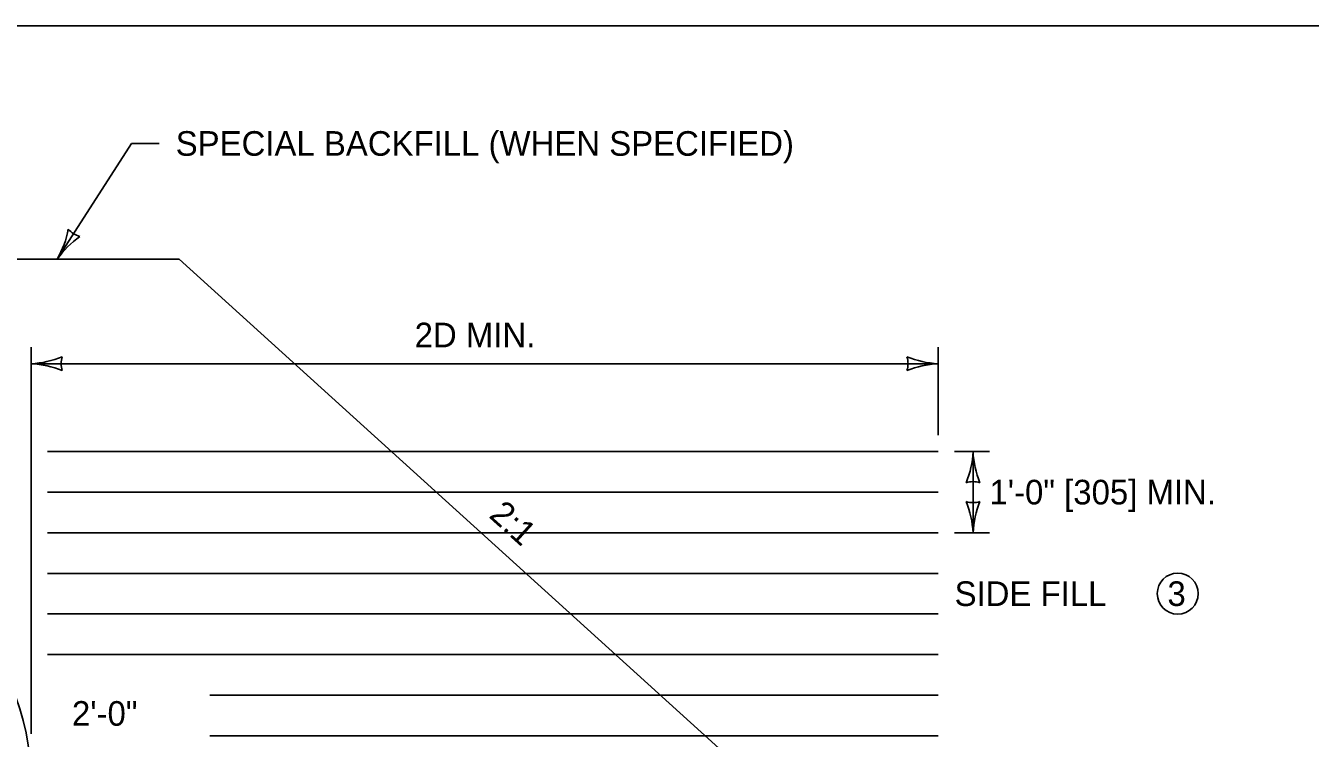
# Model space of a CAD drawing. Extents: x 49991.4 to 50021, y 49987.6 to 50011.4.
# Drawn here: x 50013.51 to 50016.641, y 50006.427 to 50008.165 of the extents above; entities that cross this region are included whole.
import ezdxf

# ---------------------------------------------------------------- set-up
doc = ezdxf.new("R2010")
doc.units = 0
for name, color, linetype in [('Level 1', 7, 'Continuous'), ('Level 2', 7, 'Continuous'), ('Level 3', 7, 'Continuous')]:
    doc.layers.add(name, color=color, linetype=linetype)

msp = doc.modelspace()

# ---------------------------------------------------------------- linework, layer by layer
at = {"layer": 'Level 1'}
for p, q in [((50013.8839, 50007.5958), (50010.1966, 50007.5958)), ((50015.8403, 50005.8238), (50013.8839, 50007.5958)), ((50013.5632, 50007.1266), (50015.7342, 50007.1266)), ((50013.5632, 50007.0276), (50015.7342, 50007.0276)), ((50013.5632, 50006.9286), (50015.7342, 50006.9286)), ((50013.5632, 50006.8296), (50015.7342, 50006.8296)), ((50013.5632, 50006.7306), (50015.7342, 50006.7306)), ((50013.5632, 50006.6316), (50015.7342, 50006.6316)), ((50013.9592, 50006.5326), (50015.7342, 50006.5326)), ((50013.9592, 50006.4336), (50015.7342, 50006.4336))]:
    msp.add_line(p, q, dxfattribs=at)
msp.add_lwpolyline([(50020.9378, 50008.1646), (50009.7374, 50008.1646), (50009.7374, 49999.8856), (50020.9378, 49999.8856)], close=True, dxfattribs=at)
msp.add_circle((50012.9127, 50006.3181), 0.6105, dxfattribs=at)
at = {"layer": 'Level 2'}
msp.add_circle((50016.3182, 50006.7801), 0.05, dxfattribs=at)
at = {"layer": 'Level 3'}
for p, q in [((50013.7679, 50007.8775), (50013.587, 50007.5958)), ((50013.7679, 50007.8775), (50013.8357, 50007.8775)), ((50013.7679, 50007.8775), (50013.8357, 50007.8775)), ((50013.7679, 50007.8775), (50013.8357, 50007.8775)), ((50013.5232, 50006.4381), (50013.5232, 50007.3806)), ((50015.7342, 50007.1666), (50015.7342, 50007.3806)), ((50013.5232, 50007.3406), (50015.7342, 50007.3406)), ((50015.7742, 50007.1266), (50015.8592, 50007.1266)), ((50015.8192, 50007.1266), (50015.8192, 50006.9286)), ((50015.7742, 50006.9286), (50015.8592, 50006.9286))]:
    msp.add_line(p, q, dxfattribs=at)
for centre, radius, start, end in [((50013.3951, 50007.7081), 0.2223, 329.6515, 349.835), ((50013.6562, 50007.7037), 0.0548, 219.4298, 255.1522), ((50013.7766, 50007.4604), 0.233, 125.2138, 144.4637), ((50013.5117, 50007.5734), 0.233, 272.8273, 292.0772), ((50013.6514, 50007.3406), 0.0548, 162.1388, 197.8612), ((50015.7434, 50007.5628), 0.2223, 247.456, 267.6395), ((50015.606, 50007.3406), 0.0548, 342.1388, 17.8612), ((50013.5141, 50007.1185), 0.2223, 67.456, 87.6395), ((50015.7457, 50007.1079), 0.233, 92.8273, 112.0772), ((50015.5971, 50007.1358), 0.2223, 337.456, 357.6395), ((50016.0519, 50007.1381), 0.233, 182.8273, 202.0772), ((50015.8192, 50006.9984), 0.0548, 72.1388, 107.8612), ((50015.8192, 50007.0568), 0.0548, 252.1388, 287.8612), ((50015.5865, 50006.9171), 0.233, 2.8273, 22.0772), ((50016.0414, 50006.9195), 0.2223, 157.456, 177.6395)]:
    msp.add_arc(centre, radius, start, end, dxfattribs=at)

# ---------------------------------------------------------------- texts
at = {"layer": 'Level 2'}
for s, p in [('SPECIAL BACKFILL (WHEN SPECIFIED)', (50013.8757, 50007.8475)), ('SPECIAL BACKFILL (WHEN SPECIFIED)', (50013.8757, 50007.8475)), ('SPECIAL BACKFILL (WHEN SPECIFIED)', (50013.8757, 50007.8475)), ('2D MIN.', (50014.4581, 50007.3806)), ('1\'-0" [305] MIN.', (50015.8592, 50006.9976)), ('SIDE FILL', (50015.7742, 50006.7501)), ('3', (50016.293, 50006.7501)), ('2\'-0"', (50013.6228, 50006.4581))]:
    msp.add_text(s, height=0.06, dxfattribs=at).set_placement(p)
msp.add_text('2:1', height=0.06, rotation=317.8325, dxfattribs=at).set_placement((50014.6369, 50006.9678))

doc.saveas('drawing.dxf')
